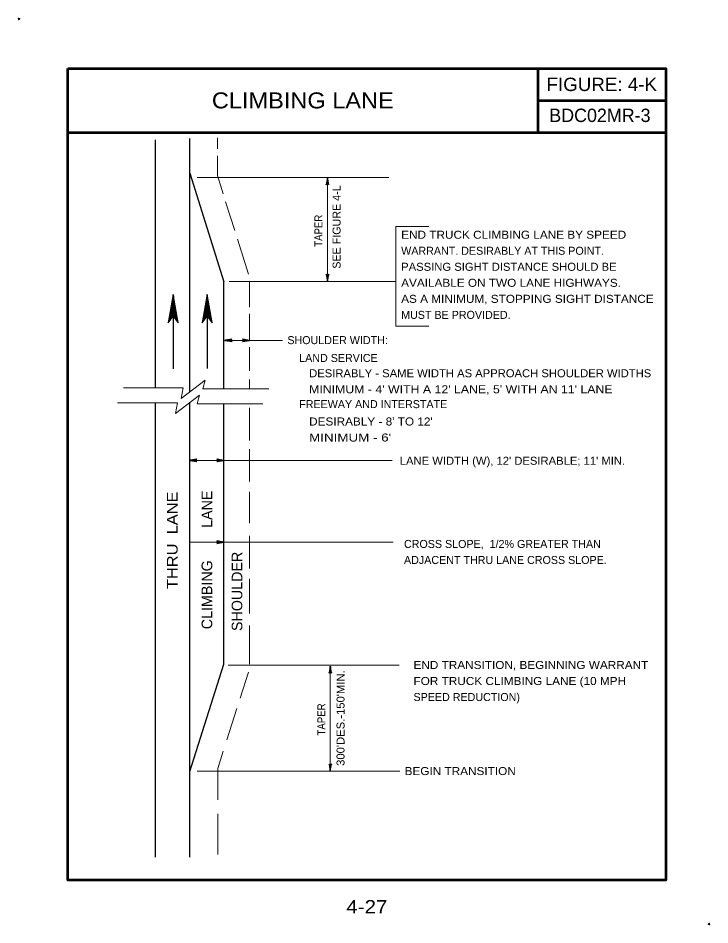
# Model space of a CAD drawing. Extents: x -2.01 to -1.335, y 2.099 to 2.983.
import ezdxf
from ezdxf.enums import TextEntityAlignment as Align

# ---------------------------------------------------------------- set-up
doc = ezdxf.new("R2010")
doc.units = 0
doc.header["$LTSCALE"] = 0.0031
doc.header["$PDMODE"] = 32
doc.header["$PDSIZE"] = 0.00155
doc.layers.add('1', color=7, linetype='Continuous', lineweight=13)
doc.layers.add('24', color=7, linetype='Continuous', lineweight=25)

msp = doc.modelspace()

# ---------------------------------------------------------------- linework, layer by layer
at = {"layer": '1', "lineweight": 53}
for p, q in [((-1.502675, 2.93425), (-1.502675, 2.87175)), ((-1.502675, 2.903), (-1.377675, 2.903)), ((-1.961008, 2.87175), (-1.377675, 2.87175))]:
    msp.add_line(p, q, dxfattribs=at)
at = {"layer": '1', "lineweight": 25}
for p, q in [((-1.8754, 2.622708), (-1.8754, 2.864433)), ((-1.842067, 2.618542), (-1.842067, 2.865792)), ((-1.842067, 2.831958), (-1.808733, 2.726192)), ((-1.808733, 2.621475), (-1.808733, 2.726192)), ((-1.858167, 2.7138), (-1.8582, 2.641392)), ((-1.825117, 2.713783), (-1.82515, 2.641625)), ((-1.8754, 2.165292), (-1.8754, 2.608183)), ((-1.842067, 2.165292), (-1.842067, 2.608692)), ((-1.808733, 2.353275), (-1.808733, 2.607233)), ((-1.842067, 2.248625), (-1.808733, 2.353275))]:
    msp.add_line(p, q, dxfattribs=at)
at = {"layer": '1'}
for p, q in [((-1.815167, 2.855625), (-1.815175, 2.86635)), ((-1.815125, 2.8297), (-1.815158, 2.849058)), ((-1.815125, 2.8297), (-1.809508, 2.811875)), ((-1.835033, 2.827792), (-1.647908, 2.827792)), ((-1.707817, 2.827742), (-1.707817, 2.726658)), ((-1.807108, 2.804242), (-1.798283, 2.776233)), ((-1.640983, 2.682958), (-1.640983, 2.780075)), ((-1.640983, 2.780075), (-1.60885, 2.780075)), ((-1.795608, 2.767742), (-1.784875, 2.7337)), ((-1.803617, 2.726517), (-1.640983, 2.726517)), ((-1.783733, 2.701333), (-1.783733, 2.726192)), ((-1.783733, 2.669442), (-1.783733, 2.694767)), ((-1.640983, 2.682958), (-1.60885, 2.682958)), ((-1.783733, 2.639433), (-1.783733, 2.662408)), ((-1.783733, 2.621708), (-1.783733, 2.630992)), ((-1.848542, 2.622708), (-1.906875, 2.622708)), ((-1.854167, 2.608183), (-1.9125, 2.608183)), ((-1.783733, 2.571433), (-1.783733, 2.603183)), ((-1.783733, 2.531567), (-1.783733, 2.562983)), ((-1.842025, 2.552042), (-1.808733, 2.552042)), ((-1.808733, 2.552042), (-1.644625, 2.552042)), ((-1.783733, 2.490767), (-1.783733, 2.521242)), ((-1.783733, 2.446683), (-1.783733, 2.478567)), ((-1.783733, 2.4026), (-1.783733, 2.436367)), ((-1.783733, 2.353275), (-1.783733, 2.390875)), ((-1.80455, 2.352275), (-1.63795, 2.352275)), ((-1.793008, 2.320242), (-1.784908, 2.345683)), ((-1.704992, 2.351483), (-1.704992, 2.249075)), ((-1.805925, 2.279692), (-1.79625, 2.310067)), ((-1.814858, 2.251658), (-1.809442, 2.268658)), ((-1.835033, 2.2491), (-1.637117, 2.2491)), ((-1.814858, 2.251658), (-1.8148, 2.221117)), ((-1.814783, 2.207517), (-1.814717, 2.167658))]:
    msp.add_line(p, q, dxfattribs=at)
at = {"layer": '1', "lineweight": 53}
msp.add_lwpolyline([(-1.961008, 2.93425), (-1.377675, 2.93425), (-1.377675, 2.142583), (-1.961008, 2.142583)], close=True, dxfattribs=at)
at = {"layer": '1'}
for points in [[(-1.807842, 2.669058), (-1.783733, 2.669058), (-1.7516, 2.669058)], [(-1.848542, 2.622708), (-1.850417, 2.612392), (-1.826967, 2.630208), (-1.829325, 2.621767), (-1.765083, 2.621767)], [(-1.854167, 2.608183), (-1.856042, 2.597858), (-1.832592, 2.615683), (-1.83495, 2.607233), (-1.770708, 2.607233)], [(-1.841608, 2.472325), (-1.808733, 2.472325), (-1.643692, 2.472325)]]:
    msp.add_lwpolyline(points, dxfattribs=at)
for p in [(-2.008808, 2.982425), (-1.335475, 2.099925)]:
    msp.add_point(p, dxfattribs=at)
at = {"layer": '24'}
for points in [[(-1.707817, 2.827742), (-1.709042, 2.820808), (-1.707817, 2.822467), (-1.706608, 2.82085), (-1.707817, 2.827742), (-1.707808, 2.827283), (-1.70895, 2.821008), (-1.7078, 2.8226), (-1.706708, 2.821125), (-1.707783, 2.827033), (-1.707817, 2.8268), (-1.708775, 2.821425), (-1.7078, 2.822633), (-1.706858, 2.821392), (-1.707817, 2.8267), (-1.707783, 2.826467), (-1.708633, 2.821767), (-1.707817, 2.822683), (-1.706975, 2.82175), (-1.707783, 2.8258), (-1.707783, 2.825408), (-1.708458, 2.822117), (-1.707833, 2.822758), (-1.70715, 2.822067), (-1.707817, 2.825333), (-1.707842, 2.824967), (-1.708258, 2.822492), (-1.707783, 2.822967), (-1.707308, 2.82245), (-1.707817, 2.824625), (-1.70785, 2.824275), (-1.708133, 2.822792), (-1.7078, 2.823033), (-1.707433, 2.822633), (-1.707817, 2.8241), (-1.70805, 2.823125), (-1.707783, 2.823267), (-1.707517, 2.822842), (-1.707783, 2.82385), (-1.707942, 2.823217), (-1.707733, 2.823483), (-1.707608, 2.823175), (-1.7078, 2.823483), (-1.707833, 2.823325)], [(-1.707817, 2.726658), (-1.706592, 2.733592), (-1.707817, 2.731933), (-1.709025, 2.73355), (-1.707817, 2.726658), (-1.707833, 2.727117), (-1.706683, 2.733392), (-1.707833, 2.7318), (-1.708925, 2.733275), (-1.70785, 2.727367), (-1.707817, 2.7276), (-1.706858, 2.732975), (-1.707833, 2.731767), (-1.708775, 2.733008), (-1.707817, 2.7277), (-1.70785, 2.727933), (-1.707, 2.732633), (-1.707817, 2.731717), (-1.708658, 2.73265), (-1.70785, 2.7286), (-1.70785, 2.728992), (-1.707175, 2.732283), (-1.7078, 2.731642), (-1.708483, 2.732333), (-1.707817, 2.729067), (-1.707792, 2.729433), (-1.707375, 2.731908), (-1.70785, 2.731433), (-1.708325, 2.73195), (-1.707817, 2.729775), (-1.707783, 2.730125), (-1.7075, 2.731608), (-1.707833, 2.731367), (-1.7082, 2.731767), (-1.707817, 2.7303), (-1.707583, 2.731275), (-1.70785, 2.731133), (-1.708117, 2.731558), (-1.70785, 2.73055), (-1.707692, 2.731183), (-1.7079, 2.730917), (-1.708025, 2.731225), (-1.707833, 2.730917), (-1.7078, 2.731075)], [(-1.858167, 2.7138), (-1.863083, 2.686083), (-1.858175, 2.6927), (-1.853358, 2.686225), (-1.858167, 2.7138), (-1.858117, 2.711958), (-1.862717, 2.686858), (-1.858117, 2.693217), (-1.853733, 2.687342), (-1.858033, 2.710967), (-1.858167, 2.710042), (-1.862, 2.688542), (-1.858117, 2.693367), (-1.854358, 2.6884), (-1.858175, 2.709617), (-1.858033, 2.7087), (-1.861433, 2.689908), (-1.858183, 2.693558), (-1.8548, 2.689825), (-1.858033, 2.706025), (-1.858033, 2.704458), (-1.860733, 2.6913), (-1.858258, 2.693858), (-1.8555, 2.6911), (-1.858175, 2.704183), (-1.858258, 2.7027), (-1.859958, 2.6928), (-1.858033, 2.694708), (-1.856142, 2.692642), (-1.858175, 2.701342), (-1.858317, 2.699942), (-1.85945, 2.694), (-1.858117, 2.694983), (-1.856633, 2.693358), (-1.858175, 2.699217), (-1.8591, 2.695342), (-1.858042, 2.6959), (-1.856975, 2.6942), (-1.858033, 2.698242), (-1.858675, 2.6957), (-1.857833, 2.696767), (-1.857333, 2.695542), (-1.858117, 2.696758), (-1.858258, 2.696125)], [(-1.825117, 2.713783), (-1.830033, 2.686067), (-1.825125, 2.692683), (-1.820308, 2.686208), (-1.825117, 2.713783), (-1.825067, 2.711942), (-1.829667, 2.686842), (-1.825067, 2.6932), (-1.820683, 2.687325), (-1.824983, 2.71095), (-1.825117, 2.710025), (-1.82895, 2.688525), (-1.825067, 2.69335), (-1.821308, 2.688383), (-1.825125, 2.7096), (-1.824983, 2.708683), (-1.828383, 2.689892), (-1.825133, 2.693542), (-1.82175, 2.689808), (-1.824983, 2.706008), (-1.824983, 2.704442), (-1.827683, 2.691283), (-1.825208, 2.693842), (-1.82245, 2.691083), (-1.825125, 2.704167), (-1.825208, 2.702683), (-1.826908, 2.692783), (-1.824983, 2.694692), (-1.823092, 2.692625), (-1.825125, 2.701325), (-1.825267, 2.699925), (-1.8264, 2.693983), (-1.825067, 2.694967), (-1.823583, 2.693342), (-1.825125, 2.6992), (-1.82605, 2.695325), (-1.824992, 2.695883), (-1.823925, 2.694183), (-1.824983, 2.698225), (-1.825625, 2.695683), (-1.824783, 2.69675), (-1.824283, 2.695525), (-1.825067, 2.696742), (-1.825208, 2.696108)], [(-1.807842, 2.669058), (-1.800908, 2.667833), (-1.802567, 2.669058), (-1.80095, 2.670267), (-1.807842, 2.669058), (-1.807383, 2.669075), (-1.801108, 2.667925), (-1.8027, 2.669075), (-1.801225, 2.670167), (-1.807133, 2.669092), (-1.8069, 2.669058), (-1.801525, 2.6681), (-1.802733, 2.669075), (-1.801492, 2.670017), (-1.8068, 2.669058), (-1.806567, 2.669092), (-1.801867, 2.668242), (-1.802783, 2.669058), (-1.80185, 2.6699), (-1.8059, 2.669092), (-1.805508, 2.669092), (-1.802217, 2.668417), (-1.802858, 2.669042), (-1.802167, 2.669725), (-1.805433, 2.669058), (-1.805067, 2.669033), (-1.802592, 2.668617), (-1.803067, 2.669092), (-1.80255, 2.669567), (-1.804725, 2.669058), (-1.804375, 2.669025), (-1.802892, 2.668742), (-1.803133, 2.669075), (-1.802733, 2.669442), (-1.8042, 2.669058), (-1.803225, 2.668825), (-1.803367, 2.669092), (-1.802942, 2.669358), (-1.80395, 2.669092), (-1.803317, 2.668933), (-1.803583, 2.669142), (-1.803275, 2.669267), (-1.803583, 2.669075), (-1.803425, 2.669042)], [(-1.783733, 2.669058), (-1.790667, 2.670283), (-1.789008, 2.669058), (-1.790625, 2.66785), (-1.783733, 2.669058), (-1.784192, 2.66905), (-1.790467, 2.670192), (-1.788875, 2.669042), (-1.79035, 2.66795), (-1.784442, 2.669025), (-1.784675, 2.669058), (-1.79005, 2.670017), (-1.788842, 2.669042), (-1.790083, 2.6681), (-1.784775, 2.669058), (-1.785008, 2.669025), (-1.789708, 2.669875), (-1.788792, 2.669058), (-1.789725, 2.668217), (-1.785675, 2.669025), (-1.786067, 2.669025), (-1.789358, 2.6697), (-1.788717, 2.669075), (-1.789408, 2.668392), (-1.786142, 2.669058), (-1.786508, 2.669083), (-1.788983, 2.6695), (-1.788508, 2.669025), (-1.789025, 2.66855), (-1.78685, 2.669058), (-1.7872, 2.669092), (-1.788683, 2.669375), (-1.788442, 2.669042), (-1.788842, 2.668675), (-1.787375, 2.669058), (-1.78835, 2.669292), (-1.788208, 2.669025), (-1.788633, 2.668758), (-1.787625, 2.669025), (-1.788258, 2.669183), (-1.787992, 2.668975), (-1.7883, 2.66885), (-1.787992, 2.669042), (-1.78815, 2.669075)], [(-1.842025, 2.552042), (-1.835092, 2.550817), (-1.83675, 2.552042), (-1.835133, 2.55325), (-1.842025, 2.552042), (-1.841567, 2.552058), (-1.835292, 2.550908), (-1.836883, 2.552058), (-1.835408, 2.55315), (-1.841317, 2.552075), (-1.841083, 2.552042), (-1.835708, 2.551083), (-1.836917, 2.552058), (-1.835675, 2.553), (-1.840983, 2.552042), (-1.84075, 2.552075), (-1.83605, 2.551225), (-1.836967, 2.552042), (-1.836033, 2.552883), (-1.840083, 2.552075), (-1.839692, 2.552075), (-1.8364, 2.5514), (-1.837042, 2.552025), (-1.83635, 2.552708), (-1.839617, 2.552042), (-1.83925, 2.552017), (-1.836775, 2.5516), (-1.83725, 2.552075), (-1.836733, 2.55255), (-1.838908, 2.552042), (-1.838558, 2.552008), (-1.837075, 2.551725), (-1.837317, 2.552058), (-1.836917, 2.552425), (-1.838383, 2.552042), (-1.837408, 2.551808), (-1.83755, 2.552075), (-1.837125, 2.552342), (-1.838133, 2.552075), (-1.8375, 2.551917), (-1.837767, 2.552125), (-1.837458, 2.55225), (-1.837767, 2.552058), (-1.837608, 2.552025)], [(-1.808733, 2.552042), (-1.815667, 2.553267), (-1.814008, 2.552042), (-1.815625, 2.550833), (-1.808733, 2.552042), (-1.809192, 2.552033), (-1.815467, 2.553175), (-1.813875, 2.552025), (-1.81535, 2.550933), (-1.809442, 2.552008), (-1.809675, 2.552042), (-1.81505, 2.553), (-1.813842, 2.552025), (-1.815083, 2.551083), (-1.809775, 2.552042), (-1.810008, 2.552008), (-1.814708, 2.552858), (-1.813792, 2.552042), (-1.814725, 2.5512), (-1.810675, 2.552008), (-1.811067, 2.552008), (-1.814358, 2.552683), (-1.813717, 2.552058), (-1.814408, 2.551375), (-1.811142, 2.552042), (-1.811508, 2.552067), (-1.813983, 2.552483), (-1.813508, 2.552008), (-1.814025, 2.551533), (-1.81185, 2.552042), (-1.8122, 2.552075), (-1.813683, 2.552358), (-1.813442, 2.552025), (-1.813842, 2.551658), (-1.812375, 2.552042), (-1.81335, 2.552275), (-1.813208, 2.552008), (-1.813633, 2.551742), (-1.812625, 2.552008), (-1.813258, 2.552167), (-1.812992, 2.551958), (-1.8133, 2.551833), (-1.812992, 2.552025), (-1.81315, 2.552058)], [(-1.808733, 2.472325), (-1.815667, 2.47355), (-1.814008, 2.472325), (-1.815625, 2.471117), (-1.808733, 2.472325), (-1.809192, 2.472317), (-1.815467, 2.473458), (-1.813875, 2.472308), (-1.81535, 2.471217), (-1.809442, 2.472292), (-1.809675, 2.472325), (-1.81505, 2.473283), (-1.813842, 2.472308), (-1.815083, 2.471367), (-1.809775, 2.472325), (-1.810008, 2.472292), (-1.814708, 2.473142), (-1.813792, 2.472325), (-1.814725, 2.471483), (-1.810675, 2.472292), (-1.811067, 2.472292), (-1.814358, 2.472967), (-1.813717, 2.472342), (-1.814408, 2.471658), (-1.811142, 2.472325), (-1.811508, 2.47235), (-1.813983, 2.472767), (-1.813508, 2.472292), (-1.814025, 2.471817), (-1.81185, 2.472325), (-1.8122, 2.472358), (-1.813683, 2.472642), (-1.813442, 2.472308), (-1.813842, 2.471942), (-1.812375, 2.472325), (-1.81335, 2.472558), (-1.813208, 2.472292), (-1.813633, 2.472025), (-1.812625, 2.472292), (-1.813258, 2.47245), (-1.812992, 2.472242), (-1.8133, 2.472117), (-1.812992, 2.472308), (-1.81315, 2.472342)], [(-1.704992, 2.351483), (-1.706217, 2.34455), (-1.704992, 2.346208), (-1.703783, 2.344592), (-1.704992, 2.351483), (-1.704983, 2.351025), (-1.706125, 2.34475), (-1.704975, 2.346342), (-1.703883, 2.344867), (-1.704958, 2.350775), (-1.704992, 2.350542), (-1.70595, 2.345167), (-1.704975, 2.346375), (-1.704033, 2.345133), (-1.704992, 2.350442), (-1.704958, 2.350208), (-1.705808, 2.345508), (-1.704992, 2.346425), (-1.70415, 2.345492), (-1.704958, 2.349542), (-1.704958, 2.34915), (-1.705633, 2.345858), (-1.705008, 2.3465), (-1.704325, 2.345808), (-1.704992, 2.349075), (-1.705017, 2.348708), (-1.705433, 2.346233), (-1.704958, 2.346708), (-1.704483, 2.346192), (-1.704992, 2.348367), (-1.705025, 2.348017), (-1.705308, 2.346533), (-1.704975, 2.346775), (-1.704608, 2.346375), (-1.704992, 2.347842), (-1.705225, 2.346867), (-1.704958, 2.347008), (-1.704692, 2.346583), (-1.704958, 2.347592), (-1.705117, 2.346958), (-1.704908, 2.347225), (-1.704783, 2.346917), (-1.704975, 2.347225), (-1.705008, 2.347067)], [(-1.704992, 2.249075), (-1.703767, 2.256008), (-1.704992, 2.25435), (-1.7062, 2.255967), (-1.704992, 2.249075), (-1.705008, 2.249533), (-1.703858, 2.255808), (-1.705008, 2.254217), (-1.7061, 2.255692), (-1.705025, 2.249783), (-1.704992, 2.250017), (-1.704033, 2.255392), (-1.705008, 2.254183), (-1.70595, 2.255425), (-1.704992, 2.250117), (-1.705025, 2.25035), (-1.704175, 2.25505), (-1.704992, 2.254133), (-1.705833, 2.255067), (-1.705025, 2.251017), (-1.705025, 2.251408), (-1.70435, 2.2547), (-1.704975, 2.254058), (-1.705658, 2.25475), (-1.704992, 2.251483), (-1.704967, 2.25185), (-1.70455, 2.254325), (-1.705025, 2.25385), (-1.7055, 2.254367), (-1.704992, 2.252192), (-1.704958, 2.252542), (-1.704675, 2.254025), (-1.705008, 2.253783), (-1.705375, 2.254183), (-1.704992, 2.252717), (-1.704758, 2.253692), (-1.705025, 2.25355), (-1.705292, 2.253975), (-1.705025, 2.252967), (-1.704867, 2.2536), (-1.705075, 2.253333), (-1.7052, 2.253642), (-1.705008, 2.253333), (-1.704975, 2.253492)]]:
    msp.add_lwpolyline(points, dxfattribs=at)

# ---------------------------------------------------------------- texts
at = {"layer": '1'}
for s, height, width, p in [('FIGURE: 4-K', 0.01303, 1.05, (-1.440175, 2.912108)), ('CLIMBING LANE', 0.01562, 1.1, (-1.731842, 2.895183)), ("LANE WIDTH (W), 12' DESIRABLE; 11' MIN.", 0.007808, 1.05, (-1.527317, 2.547742)), ('BEGIN TRANSITION', 0.007808, 1.1, (-1.5783, 2.2452)), ('4-27', 0.01303, 1.15, (-1.669338, 2.110283))]:
    msp.add_text(s, height=height, dxfattribs=dict(at, width=width)).set_placement(p, align=Align.CENTER)
msp.add_text('BDC02MR-3', height=0.01303, dxfattribs=at).set_placement((-1.441987, 2.881917), align=Align.CENTER)
for s, height, p in [('SEE FIGURE 4-L', 0.007808, (-1.694967, 2.779525)), ('LANE', 0.01041, (-1.820175, 2.5044)), ('SHOULDER', 0.01041, (-1.790842, 2.424308)), ('CLIMBING', 0.01041, (-1.820175, 2.421021))]:
    msp.add_text(s, height=height, rotation=90, dxfattribs=at).set_placement(p, align=Align.CENTER)
for s, height, width, p in [('TAPER', 0.007808, 0.9, (-1.7127, 2.7759)), ('THRU  LANE', 0.01041, 1.15, (-1.853942, 2.474108)), ("300'DES.-150'MIN.", 0.007808, 1.05, (-1.691125, 2.300742)), ('TAPER', 0.007808, 0.9, (-1.709875, 2.2994))]:
    msp.add_text(s, height=height, rotation=90, dxfattribs=dict(at, width=width)).set_placement(p, align=Align.CENTER)
for s, width, p in [('END TRUCK CLIMBING LANE BY SPEED', 1.1, (-1.635875, 2.768117)), ('PASSING SIGHT DISTANCE SHOULD BE', 1.05, (-1.635875, 2.736867)), ('AVAILABLE ON TWO LANE HIGHWAYS.', 1.1, (-1.635875, 2.721242)), ('AS A MINIMUM, STOPPING SIGHT DISTANCE', 1.1, (-1.635875, 2.705617)), ('DESIRABLY - SAME WIDTH AS APPROACH SHOULDER WIDTHS', 1.05, (-1.725683, 2.633058)), ("MINIMUM - 4' WITH A 12' LANE, 5' WITH AN 11' LANE", 1.15, (-1.725683, 2.617433)), ("DESIRABLY - 8' TO 12'", 1.1, (-1.725683, 2.586017)), ("MINIMUM - 6'", 1.25, (-1.725683, 2.570392)), ('END TRANSITION, BEGINNING WARRANT', 1.1, (-1.62385, 2.348633)), ('FOR TRUCK CLIMBING LANE (10 MPH', 1.1, (-1.62385, 2.333008))]:
    msp.add_text(s, height=0.007808, dxfattribs=dict(at, width=width)).set_placement(p)
for s, p in [('WARRANT. DESIRABLY AT THIS POINT.', (-1.635875, 2.752492)), ('MUST BE PROVIDED.', (-1.635875, 2.689992)), ('SHOULDER WIDTH:', (-1.746908, 2.665358)), ('LAND SERVICE', (-1.735358, 2.647967)), ('FREEWAY AND INTERSTATE', (-1.735358, 2.602967)), ('CROSS SLOPE,  1/2% GREATER THAN', (-1.633125, 2.466633)), ('ADJACENT THRU LANE CROSS SLOPE.', (-1.633125, 2.451008)), ('SPEED REDUCTION)', (-1.62385, 2.317383))]:
    msp.add_text(s, height=0.007808, dxfattribs=at).set_placement(p)

doc.saveas('drawing.dxf')
